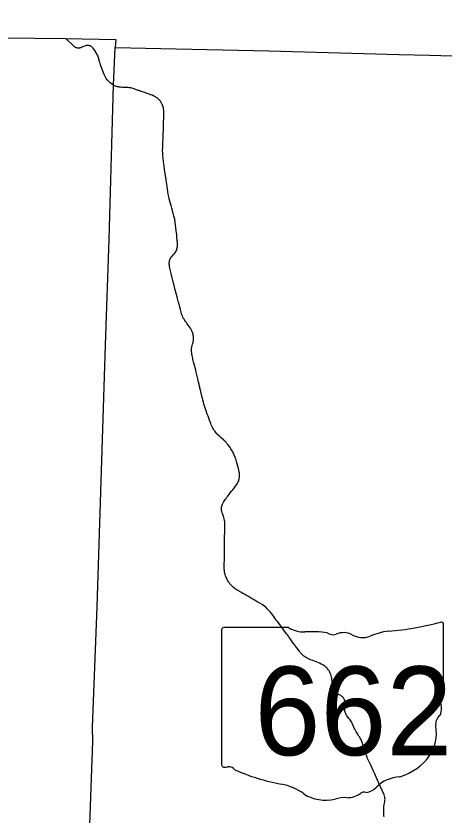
# Model space of a CAD drawing. Extents: x 1761803 to 2441803, y 509895 to 949895.
# Drawn here: x 2184428 to 2197858, y 855731 to 880821 of the extents above; entities that cross this region are included whole.
import ezdxf

# ---------------------------------------------------------------- set-up
doc = ezdxf.new("R2010")
doc.units = 0
for name, color, linetype in [('GM_X_County', 7, 'Continuous'), ('GM_X_Minor_Lake', 7, 'Continuous'), ('GM_X_Township_Road', 7, 'Continuous')]:
    doc.layers.add(name, color=color, linetype=linetype)

msp = doc.modelspace()

# ---------------------------------------------------------------- linework, layer by layer
at = {"layer": 'GM_X_County'}
for points in [[(2157996, 880821), (2161403, 880682), (2164757, 880560), (2165378, 880567), (2167835, 880460), (2171359, 880389), (2178156, 880186), (2182508, 880109), (2184039, 880132), (2185982, 880111), (2187560, 880088), (2187545, 879831), (2188970, 879800), (2192357, 879731), (2196448, 879615), (2197403, 879594), (2200215, 879512)], [(2186113, 835353), (2186167, 837910), (2186328, 842733), (2186484, 847222), (2186545, 849127), (2186623, 850541), (2186647, 851392), (2186664, 853147), (2186840, 858070), (2186832, 858518), (2186979, 862290), (2187240, 870500), (2187350, 873819), (2187490, 878652), (2187545, 879831)]]:
    msp.add_lwpolyline(points, dxfattribs=at)
at = {"layer": 'GM_X_Minor_Lake'}
for points in [[(2187490, 878652), (2187453, 878672), (2187413, 878699), (2187386, 878720), (2187350, 878752), (2187320, 878786), (2187287, 878824), (2187258, 878862), (2187232, 878904), (2187211, 878944), (2187192, 878990), (2187130, 879155), (2187092, 879259), (2187065, 879338), (2187050, 879388), (2187039, 879434), (2187020, 879510), (2187011, 879537), (2187003, 879558), (2186988, 879588), (2186973, 879617), (2186900, 879744), (2186874, 879786), (2186854, 879813), (2186843, 879825), (2186832, 879837), (2186819, 879848), (2186806, 879858), (2186792, 879867), (2186777, 879875), (2186762, 879881), (2186746, 879886), (2186730, 879890), (2186713, 879893), (2186697, 879895), (2186679, 879895), (2186664, 879895), (2186647, 879894), (2186631, 879891), (2186608, 879886), (2186581, 879877), (2186523, 879853), (2186492, 879839), (2186460, 879827), (2186432, 879820), (2186416, 879816), (2186401, 879815), (2186385, 879814), (2186369, 879815), (2186353, 879817), (2186337, 879820), (2186322, 879825), (2186309, 879830), (2186294, 879836), (2186280, 879845), (2186264, 879855), (2186244, 879870), (2186228, 879884), (2185989, 880111)], [(2187490, 878652), (2187453, 878672), (2187413, 878699), (2187386, 878720), (2187350, 878752), (2187320, 878786), (2187287, 878824), (2187258, 878862), (2187232, 878904), (2187211, 878944), (2187192, 878990), (2187130, 879155), (2187092, 879259), (2187065, 879338), (2187050, 879388), (2187039, 879434), (2187020, 879510), (2187011, 879537), (2187003, 879558), (2186988, 879588), (2186973, 879617), (2186900, 879744), (2186874, 879786), (2186854, 879813), (2186843, 879825), (2186832, 879837), (2186819, 879848), (2186806, 879858), (2186792, 879867), (2186777, 879875), (2186762, 879881), (2186746, 879886), (2186730, 879890), (2186713, 879893), (2186697, 879895), (2186679, 879895), (2186664, 879895), (2186647, 879894), (2186631, 879891), (2186608, 879886), (2186581, 879877), (2186523, 879853), (2186492, 879839), (2186460, 879827), (2186432, 879820), (2186416, 879816), (2186401, 879815), (2186385, 879814), (2186369, 879815), (2186353, 879817), (2186337, 879820), (2186322, 879825), (2186309, 879830), (2186294, 879836), (2186280, 879845), (2186264, 879855), (2186244, 879870), (2186228, 879884), (2185989, 880111)], [(2195977, 855709), (2195972, 855748), (2195969, 855796), (2195967, 855856), (2195967, 855930), (2195969, 855989), (2195972, 856025), (2195981, 856095), (2195988, 856132), (2196000, 856189), (2196006, 856229), (2196007, 856249), (2196005, 856285), (2196004, 856298), (2195997, 856336), (2195991, 856358), (2195979, 856396), (2195965, 856432), (2195943, 856478), (2195902, 856569), (2195880, 856617), (2195866, 856651), (2195840, 856707), (2195828, 856734), (2195813, 856765), (2195804, 856787), (2195801, 856793), (2195782, 856834), (2195767, 856866), (2195754, 856896), (2195742, 856923), (2195728, 856952), (2195683, 857054), (2195636, 857159), (2195568, 857308), (2195540, 857368), (2195518, 857412), (2195461, 857536), (2195442, 857577), (2195422, 857624), (2195404, 857668), (2195387, 857715), (2195369, 857773), (2195334, 857903), (2195315, 857970), (2195300, 858017), (2195284, 858063), (2195264, 858106), (2195240, 858153), (2195215, 858199), (2195190, 858240), (2195130, 858324), (2195100, 858369), (2195076, 858410), (2195056, 858450), (2195040, 858483), (2195025, 858519), (2194999, 858589), (2194977, 858641), (2194954, 858685), (2194932, 858721), (2194916, 858742), (2194876, 858790), (2194830, 858847), (2194797, 858890), (2194784, 858913), (2194774, 858932), (2194762, 858963), (2194755, 858986), (2194749, 859021), (2194746, 859057), (2194748, 859096), (2194753, 859131), (2194759, 859174), (2194764, 859219), (2194765, 859245), (2194764, 859268), (2194762, 859298), (2194756, 859322), (2194749, 859347), (2194739, 859374), (2194727, 859396), (2194704, 859432), (2194684, 859455), (2194664, 859475), (2194643, 859491), (2194618, 859506), (2194550, 859540), (2194518, 859557), (2194491, 859572), (2194479, 859580), (2194457, 859597), (2194442, 859609), (2194427, 859625), (2194411, 859646), (2194401, 859662), (2194391, 859683), (2194385, 859694), (2194381, 859707), (2194376, 859721), (2194371, 859739), (2194365, 859761), (2194361, 859781), (2194358, 859807), (2194351, 859866), (2194345, 859951), (2194340, 860007), (2194335, 860051), (2194329, 860088), (2194319, 860129), (2194309, 860164), (2194300, 860188), (2194290, 860211), (2194273, 860246), (2194252, 860283), (2194228, 860318), (2194207, 860344), (2194188, 860366), (2194162, 860393), (2194134, 860418), (2194105, 860439), (2194075, 860460), (2194049, 860475), (2194039, 860480), (2194016, 860492), (2194002, 860498), (2193946, 860524), (2193849, 860564), (2193741, 860605), (2193668, 860633), (2193606, 860660), (2193569, 860678), (2193530, 860701), (2193495, 860724), (2193463, 860749), (2193431, 860776), (2193395, 860808), (2193364, 860842), (2193338, 860872), (2193309, 860911), (2193236, 861009), (2193203, 861055), (2193184, 861082), (2193138, 861144), (2193087, 861214), (2193039, 861278), (2193000, 861330), (2192974, 861367), (2192942, 861409), (2192910, 861451), (2192810, 861589), (2192755, 861662), (2192728, 861701), (2192639, 861818), (2192596, 861876), (2192540, 861953), (2192518, 861983), (2192451, 862071), (2192404, 862130), (2192355, 862188), (2192313, 862232), (2192277, 862267), (2192239, 862299), (2192196, 862330), (2192152, 862360), (2192076, 862406), (2191999, 862450), (2191961, 862472), (2191929, 862491), (2191917, 862498), (2191891, 862513), (2191857, 862533), (2191820, 862555), (2191788, 862573), (2191751, 862596), (2191719, 862614), (2191679, 862637), (2191646, 862656), (2191613, 862675), (2191580, 862694), (2191547, 862712), (2191513, 862731), (2191478, 862751), (2191442, 862771), (2191409, 862790), (2191378, 862809), (2191348, 862827), (2191319, 862848), (2191293, 862866), (2191256, 862896), (2191229, 862920), (2191210, 862937), (2191181, 862966), (2191156, 862993), (2191140, 863014), (2191112, 863051), (2191095, 863077), (2191089, 863086), (2191080, 863101), (2191073, 863113), (2191058, 863140), (2191045, 863167), (2191039, 863179), (2191023, 863215), (2191017, 863230), (2191003, 863268), (2190992, 863302), (2190982, 863339), (2190973, 863385), (2190966, 863433), (2190962, 863481), (2190961, 863524), (2190962, 863577), (2190965, 863661), (2190966, 863744), (2190968, 863830), (2190970, 863938), (2190970, 864016), (2190970, 864088), (2190972, 864156), (2190972, 864215), (2190972, 864268), (2190972, 864314), (2190972, 864350), (2190975, 864541), (2190976, 864593), (2190978, 864657), (2190977, 864717), (2190980, 864780), (2190981, 864844), (2190981, 864893), (2190980, 864936), (2190978, 864971), (2190973, 865002), (2190963, 865050), (2190952, 865088), (2190939, 865124), (2190914, 865192), (2190897, 865239), (2190884, 865284), (2190879, 865308), (2190875, 865332), (2190874, 865357), (2190875, 865387), (2190879, 865420), (2190884, 865445), (2190895, 865480), (2190907, 865514), (2190924, 865549), (2190940, 865577), (2190961, 865610), (2190996, 865659), (2191018, 865690), (2191045, 865727), (2191070, 865759), (2191115, 865819), (2191151, 865864), (2191191, 865914), (2191227, 865960), (2191294, 866046), (2191348, 866120), (2191367, 866148), (2191382, 866174), (2191402, 866215), (2191415, 866247), (2191425, 866275), (2191433, 866307), (2191440, 866347), (2191442, 866377), (2191444, 866404), (2191443, 866435), (2191440, 866466), (2191439, 866476), (2191438, 866485), (2191433, 866515), (2191430, 866534), (2191420, 866576), (2191407, 866634), (2191360, 866809), (2191345, 866861), (2191334, 866902), (2191320, 866946), (2191303, 866992), (2191286, 867032), (2191262, 867086), (2191243, 867123), (2191218, 867174), (2191192, 867219), (2191173, 867250), (2191145, 867292), (2191119, 867329), (2191111, 867339), (2191078, 867381), (2191038, 867429), (2191008, 867463), (2190985, 867487), (2190953, 867519), (2190866, 867596), (2190824, 867632), (2190803, 867651), (2190766, 867686), (2190735, 867719), (2190703, 867755), (2190678, 867786), (2190650, 867823), (2190626, 867860), (2190608, 867891), (2190582, 867941), (2190556, 868000), (2190537, 868046), (2190519, 868092), (2190499, 868143), (2190453, 868266), (2190427, 868338), (2190392, 868434), (2190380, 868470), (2190360, 868531), (2190337, 868613), (2190310, 868711), (2190261, 868902), (2190215, 869084), (2190201, 869147), (2190193, 869176), (2190178, 869246), (2190171, 869275), (2190156, 869341), (2190134, 869440), (2190123, 869484), (2190103, 869564), (2190083, 869647), (2190066, 869710), (2190037, 869828), (2190018, 869902), (2190001, 869969), (2189982, 870050), (2189976, 870074), (2189965, 870128), (2189955, 870172), (2189949, 870202), (2189941, 870249), (2189934, 870298), (2189933, 870328), (2189935, 870354), (2189940, 870389), (2189948, 870433), (2189960, 870487), (2189971, 870532), (2189985, 870592), (2189996, 870643), (2189998, 870676), (2190000, 870703), (2190000, 870738), (2189998, 870773), (2189992, 870805), (2189985, 870838), (2189975, 870875), (2189961, 870911), (2189945, 870948), (2189925, 870986), (2189899, 871029), (2189868, 871075), (2189825, 871137), (2189803, 871165), (2189773, 871204), (2189748, 871238), (2189724, 871273), (2189701, 871309), (2189678, 871345), (2189659, 871384), (2189639, 871429), (2189625, 871471), (2189619, 871487), (2189606, 871536), (2189585, 871615), (2189559, 871726), (2189533, 871825), (2189521, 871871), (2189509, 871915), (2189496, 871964), (2189483, 872013), (2189458, 872115), (2189427, 872234), (2189394, 872364), (2189365, 872484), (2189322, 872651), (2189299, 872745), (2189260, 872910), (2189248, 872969), (2189241, 873005), (2189237, 873035), (2189235, 873059), (2189235, 873070), (2189236, 873093), (2189240, 873122), (2189249, 873153), (2189257, 873177), (2189269, 873204), (2189281, 873227), (2189298, 873253), (2189319, 873281), (2189338, 873303), (2189381, 873348), (2189413, 873385), (2189434, 873415), (2189445, 873435), (2189460, 873465), (2189472, 873496), (2189478, 873517), (2189486, 873553), (2189491, 873586), (2189494, 873625), (2189495, 873665), (2189493, 873705), (2189487, 873780), (2189478, 873871), (2189470, 873955), (2189464, 874020), (2189458, 874080), (2189447, 874180), (2189435, 874269), (2189424, 874349), (2189420, 874377), (2189412, 874424), (2189408, 874446), (2189400, 874478), (2189384, 874545), (2189340, 874716), (2189319, 874798), (2189296, 874880), (2189280, 874936), (2189257, 875019), (2189238, 875089), (2189224, 875150), (2189206, 875237), (2189193, 875318), (2189180, 875399), (2189150, 875607), (2189142, 875669), (2189137, 875702), (2189122, 875807), (2189111, 875881), (2189101, 875945), (2189092, 876011), (2189077, 876110), (2189066, 876180), (2189056, 876248), (2189052, 876283), (2189044, 876344), (2189042, 876372), (2189036, 876434), (2189031, 876516), (2189030, 876607), (2189031, 876691), (2189035, 876772), (2189038, 876871), (2189042, 876956), (2189045, 877014), (2189048, 877066), (2189050, 877117), (2189051, 877166), (2189052, 877211), (2189053, 877285), (2189055, 877354), (2189057, 877429), (2189059, 877477), (2189060, 877522), (2189063, 877587), (2189064, 877617), (2189069, 877745), (2189070, 877811), (2189068, 877847), (2189067, 877860), (2189061, 877905), (2189054, 877939), (2189050, 877955), (2189042, 877982), (2189037, 877998), (2189031, 878015), (2189017, 878048), (2188998, 878090), (2188988, 878108), (2188976, 878127), (2188962, 878146), (2188943, 878168), (2188925, 878187), (2188913, 878199), (2188901, 878210), (2188888, 878223), (2188864, 878243), (2188844, 878258), (2188825, 878270), (2188805, 878283), (2188786, 878295), (2188766, 878305), (2188750, 878314), (2188737, 878320), (2188703, 878334), (2188689, 878339), (2188652, 878352), (2188602, 878370), (2188553, 878386), (2188510, 878402), (2188467, 878417), (2188402, 878439), (2188358, 878454), (2188310, 878470), (2188272, 878484), (2188253, 878491), (2188238, 878496), (2188227, 878500), (2188180, 878517), (2188153, 878528), (2188132, 878537), (2188100, 878548), (2188064, 878558), (2188029, 878567), (2187992, 878573), (2187962, 878576), (2187911, 878577), (2187856, 878576), (2187823, 878577), (2187797, 878578), (2187757, 878580), (2187723, 878584), (2187695, 878587), (2187666, 878592), (2187636, 878599), (2187610, 878604), (2187583, 878611), (2187548, 878622), (2187525, 878629), (2187506, 878637), (2187490, 878652)]]:
    msp.add_lwpolyline(points, dxfattribs=at)
at = {"layer": 'GM_X_Township_Road'}
for p, q in [((2192988, 861638), (2190949, 861638)), ((2197841, 859532), (2197841, 861743)), ((2190881, 861565), (2190881, 857339)), ((2197841, 859532), (2197841, 859532))]:
    msp.add_line(p, q, dxfattribs=at)
for centre, major_axis, start_param, end_param in [((2190960, 861574), (80.6, 0), 1.712693, 3.28349), ((2193473, 862128), (782, 0), 4.042523, 4.731795), ((2195362, 867400), (7382, 0), 4.814394, 5.042369), ((2197764, 861752), (77.5, 0), 6.141152, 7.989035), ((2193732, 859265), (2808, 0), 1.404758, 1.657858), ((2194370, 861596), (226, 0), 3.836095, 5.185415), ((2194701, 861107), (469, 0), 0.950623, 2.079405), ((2195307, 861778), (564, 0), 4.081561, 5.145723), ((2196303, 860347), (1485, 0), 1.699011, 2.107814), ((2197823, 859369), (120, 0), 1.883978, 3.671073), ((2197759, 859523), (82.9, 0), 5.05454, 6.418171), ((2197061, 859090), (720, 0), 5.934695, 6.695948), ((2198119, 858606), (524, 0), 2.387724, 3.262537), ((2195775, 858325), (1846, 0), 5.101752, 6.440018), ((2190961, 857329), (81.4, 0), 3.00124, 4.508301), ((2190973, 857762), (621, 0), 4.665946, 4.897461), ((2191100, 857095), (224, 0), 0.519207, 1.627899), ((2193927, 860892), (5331, 0), 4.195997, 4.488961), ((2196554, 856152), (1011, 0), 1.647645, 2.488434), ((2192338, 855440), (1668, 0), 0.823519, 1.323587), ((2195273, 856929), (597, 0), 4.937069, 5.64225), ((2194141, 857074), (1058, 0), 4.026481, 4.996735), ((2194830, 856757), (564, 0), 4.691044, 5.507374), ((2195340, 856348), (159, 0), 1.147584, 2.315152), ((2194753, 855612), (870, 0), 1.495662, 1.94098)]:
    msp.add_ellipse(centre, major_axis=major_axis, ratio=0.8, start_param=start_param, end_param=end_param, dxfattribs=at)

# ---------------------------------------------------------------- texts
msp.add_text('662', height=2784.4, dxfattribs=at).set_placement((2191910, 857637))

doc.saveas('drawing.dxf')
